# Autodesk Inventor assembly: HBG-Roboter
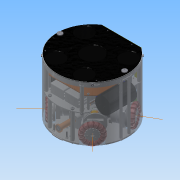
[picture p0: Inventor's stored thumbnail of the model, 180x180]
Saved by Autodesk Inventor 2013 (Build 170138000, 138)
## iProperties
Created: 2012-07
Part Number: HBG-Roboter
Document SubType Name: Assembly
Designer: rYan
Mass: 2617.21 g
Surface Area: 6839.11 cm^2
Volume: 1346.66 cm^3
Density: 1.94348 g/cm^3
Author: rYan
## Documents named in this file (22)
- D:\SVN\2013\Inventor\HBG-Roboter.iam
- D:\SVN\2013\Inventor\Antrieb\OBG-AntriebA.iam
- D:\SVN\2013\Inventor\Antrieb\OBG-AntriebB.iam
- D:\SVN\2013\Inventor\Kicker\UBG-Spulen.iam
- D:\SVN\2013\Inventor\Kicker\Straight\MG-Straight Kicker.iam
- D:\SVN\2013\Inventor\Dribbling Device\UBG-Dribbling Device.iam
- D:\SVN\2013\Inventor\Kicker\Chip\MG-Chipperschwinge.iam
- D:\SVN\2013\Inventor\Dribbling Device\UBG-Dribblerlagerbock.iam
- D:\SVN\2013\Inventor\Kicker\Chip\UBG-Chipspule.iam
- D:\SVN\2013\Inventor\Inhaltscenter\de-DE\DIN 7984\DIN 7984 - M3 x 6.ipt
- D:\SVN\2013\Inventor\Testmasse.ipt
- D:\SVN\2013\Inventor\Elektronik\OBG-Elektronik.iam
- D:\SVN\2013\Inventor\Kabel und Kabelbaum\HBG-Roboter.Kabelbaum1.iam
- D:\SVN\2013\Inventor\Inhaltscenter\de-DE\ISO 4035(2)\ISO 4035 - M3ISO.ipt
- D:\SVN\2013\Inventor\Grundplatte.ipt
- D:\SVN\2013\Inventor\Gehäuse\OBG-Gehäuse.iam
- D:\SVN\2013\Inventor\Inhaltscenter\de-DE\DIN 7984\DIN 7984 - M4 x 6.ipt
- D:\SVN\2013\Inventor\Inhaltscenter\de-DE\DIN 467\DIN 467 - M3.ipt
- D:\SVN\2013\Inventor\Inhaltscenter\en-US\DIN 7984\DIN 7984 - M4 x 6.ipt
- D:\SVN\2013\Inventor\Inhaltscenter\en-US\DIN 7984\DIN 7984 - M3 x 6.ipt
- D:\SVN\2013\Inventor\Inhaltscenter\en-US\ISO 4762(1)\ISO 4762 - M2,5 x 6DIN EN ISO.ipt
- D:\SVN\2013\Inventor\Inhaltscenter\en-US\DIN 7984\DIN 7984 - M3 x 16.ipt
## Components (63 placed, 19 different names)
1. Grundplatte:1 — Passend:1, Passend:5, Passend:6, Passend:9, Passend:24, Passend:25, Passend:31, Passend:34, Passend:35, Passend:36, Passend:37, Passend:38, Passend:39, Passend:40, Passend:41, Passend:42, Passend:44, Passend:46, Passend:48, Passend:50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
2. Testmaße:1 — Passend:114, Fluchtend:32, Passend:115
3. Kabelbaum1 [sub-assembly]
4. OBG-AntriebA:1 [sub-assembly] — Passend:1, Passend:34, Passend:35, Passend:283
5. DIN 7984 M4 x 6:5 — Passend:44
6. DIN 7984 M4 x 6:6 — Passend:46
7. DIN 7984 M4 x 6:7 — Passend:48
8. DIN 7984 M3 x 6:16 — Passend:164
9. DIN 7984 M3 x 6:17 — Passend:166
10. OBG-AntriebB:2 [sub-assembly] — Passend:6, Passend:41, Passend:42, Passend:282
11. DIN 7984 M4 x 6:8 — Passend:50
12. DIN 7984 M4 x 6:9 — Passend:52
13. DIN 7984 M4 x 6:10 — Passend:54
14. DIN 7984 M3 x 6:18 — Passend:160
15. DIN 7984 M3 x 6:19 — Passend:162
16. OBG-AntriebA:2 [sub-assembly] — Passend:36, Passend:37, Passend:38, Passend:281
17. DIN 7984 M4 x 6:11 — Passend:62
18. DIN 7984 M4 x 6:12 — Passend:64
19. DIN 7984 M4 x 6:13 — Passend:66
20. DIN 7984 M3 x 6:20 — Passend:172
21. DIN 7984 M3 x 6:21 — Passend:174
22. OBG-AntriebB:1 [sub-assembly] — Passend:5, Passend:39, Passend:40, Passend:280
23. DIN 7984 M4 x 6:14 — Passend:56
24. DIN 7984 M4 x 6:15 — Passend:58
25. DIN 7984 M4 x 6:16 — Passend:60
26. DIN 7984 M3 x 6:15 — Passend:168
27. DIN 7984 M3 x 6:22 — Passend:170
28. UBG-Chipspule:1 [sub-assembly] — Passend:277, Passend:278, Passend:279
29. MG-Chipperschwinge:1 [sub-assembly] — Passend:33, Passend:69, Winkel:6
30. UBG-Spulen:1 [sub-assembly] — Passend:9, Passend:17, Passend:18, Winkel:1, Passend:24, Passend:25
31. DIN EN ISO 4762 M2,5 x 6:1 — Passend:270
32. DIN EN ISO 4762 M2,5 x 6:2 — Passend:272
33. DIN EN ISO 4762 M2,5 x 6:3 — Passend:274
34. DIN EN ISO 4762 M2,5 x 6:4 — Passend:276
35. MG-Straight Kicker:1 [sub-assembly] — Passend:17, Passend:18, Winkel:1
36. DIN 7984 M4 x 6:1 — Passend:144
37. DIN 7984 M4 x 6:2 — Passend:146
38. DIN 7984 M4 x 6:3 — Passend:285
39. DIN 7984 M4 x 6:4 — Passend:287
40. DIN 7984 M3 x 16:1 — Einfügen:19
41. DIN 7984 M3 x 16:2 — Einfügen:23
42. ISO 4035 M3:5 — Passend:289
43. ISO 4035 M3:6 — Passend:291
44. UBG-Dribbling Device:1 [sub-assembly] — Passend:67, Passend:68, Winkel:5
45. DIN 7984 M3 x 6:5 — Passend:176
46. DIN 7984 M3 x 6:6 — Passend:178
47. DIN 7984 M3 x 6:7 — Passend:180
48. DIN 7984 M3 x 6:8 — Passend:182
49. DIN 7984 M3 x 6:9 — Passend:184
50. DIN 7984 M3 x 6:10 — Passend:186
51. UBG-Dribblerlagerbock:1 [sub-assembly] — Passend:31, Passend:33, Passend:67, Passend:68, Winkel:5, Passend:69, Passend:187, Passend:188, Winkel:6
52. OBG-Elektronik:1 [sub-assembly] — Passend:117, Passend:250, Passend:251, Passend:252, Passend:292, Passend:293, Passend:294
53. DIN 7984 M4 x 6:17 — Einfügen:41
54. DIN 7984 M4 x 6:18 — Einfügen:42
55. DIN 7984 M4 x 6:19 — Passend:140
56. DIN 7984 M4 x 6:20 — Passend:142
57. DIN 7984 M3 x 6:11 — Einfügen:33
58. DIN 7984 M3 x 6:12 — Einfügen:34
59. DIN 7984 M3 x 6:13 — Einfügen:32
60. DIN 7984 M3 x 6:14 — Einfügen:31
61. DIN 467 M3:1 — Passend:296
62. DIN 467 M3:2 — Passend:298
63. OBG-Gehäuse:1 [sub-assembly] — Passend:292, Passend:293, Passend:294, Passend:296, Passend:298
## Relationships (93: Mate 81, Insert 8, Angle 3, Flush 1)
- Passend:1 [Mate]: Grundplatte:1 ↔ OBG-AntriebA:1
- Passend:5 [Mate]: Grundplatte:1 ↔ OBG-AntriebB:1
- Passend:6 [Mate]: Grundplatte:1 ↔ OBG-AntriebB:2
- Passend:9 [Mate]: Grundplatte:1 ↔ UBG-Spulen:1
- Passend:17 [Mate]: UBG-Spulen:1 ↔ MG-Straight Kicker:1
- Passend:18 [Mate]: UBG-Spulen:1 ↔ MG-Straight Kicker:1
- Winkel:1 [Angle]: UBG-Spulen:1 ↔ MG-Straight Kicker:1
- Passend:24 [Mate]: Grundplatte:1 ↔ UBG-Spulen:1
- Passend:25 [Mate]: Grundplatte:1 ↔ UBG-Spulen:1
- Passend:31 [Mate]: Grundplatte:1 ↔ UBG-Dribblerlagerbock:1
- Passend:33 [Mate]: MG-Chipperschwinge:1 ↔ UBG-Dribblerlagerbock:1
- Passend:34 [Mate]: Grundplatte:1 ↔ OBG-AntriebA:1
- Passend:35 [Mate]: Grundplatte:1 ↔ OBG-AntriebA:1
- Passend:36 [Mate]: Grundplatte:1 ↔ OBG-AntriebA:2
- Passend:37 [Mate]: Grundplatte:1 ↔ OBG-AntriebA:2
- Passend:38 [Mate]: Grundplatte:1 ↔ OBG-AntriebA:2
- Passend:39 [Mate]: Grundplatte:1 ↔ OBG-AntriebB:1
- Passend:40 [Mate]: Grundplatte:1 ↔ OBG-AntriebB:1
- Passend:41 [Mate]: Grundplatte:1 ↔ OBG-AntriebB:2
- Passend:42 [Mate]: Grundplatte:1 ↔ OBG-AntriebB:2
- Passend:44 [Mate]: Grundplatte:1 ↔ DIN 7984 M4 x 6:5
- Passend:46 [Mate]: Grundplatte:1 ↔ DIN 7984 M4 x 6:6
- Passend:48 [Mate]: Grundplatte:1 ↔ DIN 7984 M4 x 6:7
- Passend:50 [Mate]: Grundplatte:1 ↔ DIN 7984 M4 x 6:8
- Passend:52 [Mate]: Grundplatte:1 ↔ DIN 7984 M4 x 6:9
- Passend:54 [Mate]: Grundplatte:1 ↔ DIN 7984 M4 x 6:10
- Passend:56 [Mate]: Grundplatte:1 ↔ DIN 7984 M4 x 6:14
- Passend:58 [Mate]: Grundplatte:1 ↔ DIN 7984 M4 x 6:15
- Passend:60 [Mate]: Grundplatte:1 ↔ DIN 7984 M4 x 6:16
- Passend:62 [Mate]: Grundplatte:1 ↔ DIN 7984 M4 x 6:11
- Passend:64 [Mate]: Grundplatte:1 ↔ DIN 7984 M4 x 6:12
- Passend:66 [Mate]: Grundplatte:1 ↔ DIN 7984 M4 x 6:13
- Passend:67 [Mate]: UBG-Dribbling Device:1 ↔ UBG-Dribblerlagerbock:1
- Passend:68 [Mate]: UBG-Dribbling Device:1 ↔ UBG-Dribblerlagerbock:1
- Winkel:5 [Angle]: UBG-Dribbling Device:1 ↔ UBG-Dribblerlagerbock:1
- Passend:69 [Mate]: MG-Chipperschwinge:1 ↔ UBG-Dribblerlagerbock:1
- Passend:114 [Mate]: Grundplatte:1 ↔ Testmaße:1
- Fluchtend:32 [Flush]: Grundplatte:1 ↔ Testmaße:1
- Passend:115 [Mate]: Grundplatte:1 ↔ Testmaße:1
- Passend:117 [Mate]: Grundplatte:1 ↔ OBG-Elektronik:1
- Passend:140 [Mate]: Grundplatte:1 ↔ DIN 7984 M4 x 6:19
- Passend:142 [Mate]: Grundplatte:1 ↔ DIN 7984 M4 x 6:20
- Passend:144 [Mate]: Grundplatte:1 ↔ DIN 7984 M4 x 6:1
- Passend:146 [Mate]: Grundplatte:1 ↔ DIN 7984 M4 x 6:2
- Passend:160 [Mate]: Grundplatte:1 ↔ DIN 7984 M3 x 6:18
- Passend:162 [Mate]: Grundplatte:1 ↔ DIN 7984 M3 x 6:19
- Passend:164 [Mate]: Grundplatte:1 ↔ DIN 7984 M3 x 6:16
- Passend:166 [Mate]: Grundplatte:1 ↔ DIN 7984 M3 x 6:17
- Passend:168 [Mate]: Grundplatte:1 ↔ DIN 7984 M3 x 6:15
- Passend:170 [Mate]: Grundplatte:1 ↔ DIN 7984 M3 x 6:22
- Passend:172 [Mate]: Grundplatte:1 ↔ DIN 7984 M3 x 6:20
- Passend:174 [Mate]: Grundplatte:1 ↔ DIN 7984 M3 x 6:21
- Passend:176 [Mate]: Grundplatte:1 ↔ DIN 7984 M3 x 6:5
- Passend:178 [Mate]: Grundplatte:1 ↔ DIN 7984 M3 x 6:6
- Passend:180 [Mate]: Grundplatte:1 ↔ DIN 7984 M3 x 6:7
- Passend:182 [Mate]: Grundplatte:1 ↔ DIN 7984 M3 x 6:8
- Passend:184 [Mate]: Grundplatte:1 ↔ DIN 7984 M3 x 6:9
- Passend:186 [Mate]: Grundplatte:1 ↔ DIN 7984 M3 x 6:10
- Passend:187 [Mate]: Grundplatte:1 ↔ UBG-Dribblerlagerbock:1
- Passend:188 [Mate]: Grundplatte:1 ↔ UBG-Dribblerlagerbock:1
- Winkel:6 [Angle]: MG-Chipperschwinge:1 ↔ UBG-Dribblerlagerbock:1
- Passend:203 [Mate]: Grundplatte:1
- Einfügen:19 [Insert]: Grundplatte:1 ↔ DIN 7984 M3 x 16:1
- Einfügen:23 [Insert]: Grundplatte:1 ↔ DIN 7984 M3 x 16:2
- Einfügen:31 [Insert]: Grundplatte:1 ↔ DIN 7984 M3 x 6:14
- Einfügen:32 [Insert]: Grundplatte:1 ↔ DIN 7984 M3 x 6:13
- Einfügen:33 [Insert]: Grundplatte:1 ↔ DIN 7984 M3 x 6:11
- Einfügen:34 [Insert]: Grundplatte:1 ↔ DIN 7984 M3 x 6:12
- Einfügen:41 [Insert]: Grundplatte:1 ↔ DIN 7984 M4 x 6:17
- Einfügen:42 [Insert]: Grundplatte:1 ↔ DIN 7984 M4 x 6:18
- Passend:250 [Mate]: Grundplatte:1 ↔ OBG-Elektronik:1
- Passend:251 [Mate]: Grundplatte:1 ↔ OBG-Elektronik:1
- Passend:252 [Mate]: Grundplatte:1 ↔ OBG-Elektronik:1
- Passend:270 [Mate]: Grundplatte:1 ↔ DIN EN ISO 4762 M2,5 x 6:1
- Passend:272 [Mate]: Grundplatte:1 ↔ DIN EN ISO 4762 M2,5 x 6:2
- Passend:274 [Mate]: Grundplatte:1 ↔ DIN EN ISO 4762 M2,5 x 6:3
- Passend:276 [Mate]: Grundplatte:1 ↔ DIN EN ISO 4762 M2,5 x 6:4
- Passend:277 [Mate]: Grundplatte:1 ↔ UBG-Chipspule:1
- Passend:278 [Mate]: Grundplatte:1 ↔ UBG-Chipspule:1
- Passend:279 [Mate]: Grundplatte:1 ↔ UBG-Chipspule:1
- Passend:280 [Mate]: OBG-AntriebB:1
- Passend:281 [Mate]: OBG-AntriebA:2
- Passend:282 [Mate]: OBG-AntriebB:2
- Passend:283 [Mate]: OBG-AntriebA:1
- Passend:285 [Mate]: Grundplatte:1 ↔ DIN 7984 M4 x 6:3
- Passend:287 [Mate]: Grundplatte:1 ↔ DIN 7984 M4 x 6:4
- Passend:289 [Mate]: Grundplatte:1 ↔ ISO 4035 M3:5
- Passend:291 [Mate]: Grundplatte:1 ↔ ISO 4035 M3:6
- Passend:292 [Mate]: OBG-Elektronik:1 ↔ OBG-Gehäuse:1
- Passend:293 [Mate]: OBG-Elektronik:1 ↔ OBG-Gehäuse:1
- Passend:294 [Mate]: OBG-Elektronik:1 ↔ OBG-Gehäuse:1
- Passend:296 [Mate]: DIN 467 M3:1 ↔ OBG-Gehäuse:1
- Passend:298 [Mate]: DIN 467 M3:2 ↔ OBG-Gehäuse:1
